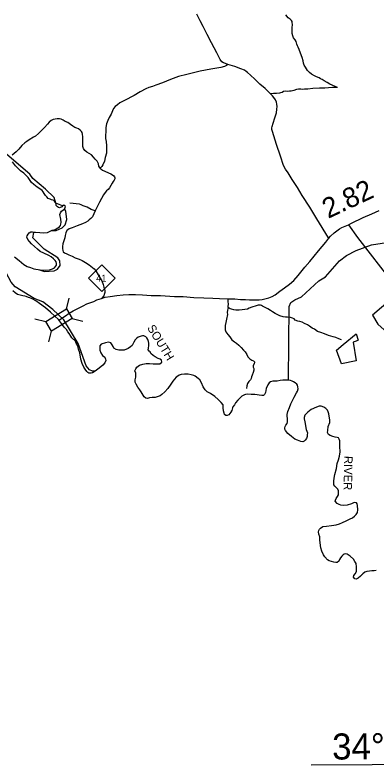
# Model space of a CAD drawing. Extents: x 2093524 to 2270757, y 289120 to 570408.
# Drawn here: x 2188536 to 2197553, y 334062 to 352773 of the extents above; entities that cross this region are included whole.
import ezdxf

# ---------------------------------------------------------------- set-up
doc = ezdxf.new("R2010")
doc.units = 0
for name, color, linetype in [('Exist Boundary Political CountyLine', 7, 'Continuous'), ('Exist Hydrographic Creek Single Shore', 7, 'Continuous'), ('Exist Hydrographic Lagoon', 7, 'Continuous'), ('Exist Hydrographic Misc Water Feature', 7, 'Continuous'), ('Exist Hydrographic River Shore Label', 7, 'Continuous'), ('Exist Road Non-System Type 51', 7, 'Continuous'), ('Exist Road Primary NC Attributed', 7, 'Continuous'), ('Exist Road Primary NC Service Mileage Hundredths English Label', 7, 'Continuous'), ('Exist Road Primary NC Shield CELL', 7, 'Continuous'), ('Exist Road Primary NC Shield Number Label', 7, 'Continuous'), ('Exist Road Primary NC Structure Standard Bridge CELL', 7, 'Continuous'), ('Map Preparation Longitude Latitude Label', 7, 'Continuous'), ('Map Preparation Longitude Latitude Lines', 7, 'Continuous')]:
    doc.layers.add(name, color=color, linetype=linetype)

msp = doc.modelspace()

# ---------------------------------------------------------------- linework, layer by layer
at = {"layer": 'Exist Boundary Political CountyLine'}
for points in [[(2189050, 347357), (2189159, 347345), (2189256, 347337), (2189346, 347350), (2189465, 347403), (2189536, 347422), (2189606, 347459), (2189645, 347490), (2189672, 347520), (2189681, 347554), (2189686, 347605), (2189681, 347680), (2189657, 347799), (2189669, 347838), (2189696, 347879), (2189758, 347922), (2189784, 347949), (2189797, 347997), (2189758, 348031), (2189734, 348017), (2189702, 347988), (2189651, 347958), (2189619, 347968), (2189598, 347988), (2189568, 348019), (2189561, 348068), (2189537, 348104), (2189512, 348145), (2189481, 348153), (2189449, 348158), (2189413, 348175), (2189362, 348194), (2189328, 348233), (2189296, 348267), (2189264, 348318), (2189240, 348357), (2189211, 348396), (2189160, 348437), (2189094, 348474), (2189007, 348542), (2188951, 348598), (2188915, 348646), (2188868, 348717), (2188818, 348770), (2188759, 348824), (2188672, 348887), (2188616, 348943), (2188552, 349006), (2188470, 349108)], [(2188527, 346739), (2188639, 346647), (2188753, 346550), (2188840, 346496), (2188921, 346470), (2189008, 346436), (2189161, 346416), (2189300, 346404), (2189394, 346414), (2189472, 346436), (2189521, 346467), (2189552, 346501), (2189572, 346535), (2189574, 346572), (2189565, 346611), (2189538, 346650), (2189502, 346686), (2189441, 346739), (2189378, 346776), (2189256, 346832), (2189166, 346871), (2189100, 346931), (2189025, 347000), (2188950, 347063), (2188899, 347121), (2188860, 347172), (2188836, 347230), (2188843, 347264), (2188862, 347303), (2188887, 347335), (2188935, 347364), (2188972, 347364), (2189050, 347357)], [(2190798, 344186), (2190803, 344150), (2190776, 344094), (2190734, 344040), (2190640, 343965), (2190538, 343885), (2190470, 343846), (2190436, 343836), (2190406, 343836), (2190380, 343841), (2190353, 343856), (2190329, 343882), (2190292, 343933), (2190258, 343989), (2190212, 344079), (2190178, 344186), (2190152, 344342), (2190125, 344439), (2190103, 344517), (2190064, 344587), (2190035, 344650), (2190001, 344677), (2189957, 344721), (2189935, 344762), (2189889, 344825), (2189860, 344872), (2189821, 344928), (2189763, 344981), (2189719, 345044), (2189622, 345173), (2189534, 345260), (2189427, 345358), (2189294, 345470), (2189150, 345572), (2189053, 345640), (2188978, 345683), (2188907, 345713), (2188874, 345728), (2188819, 345750), (2188780, 345762), (2188734, 345770), (2188666, 345782), (2188600, 345801), (2188544, 345838), (2188481, 345894)], [(2193833, 342781), (2193801, 342781), (2193772, 342806), (2193757, 342842), (2193745, 342901), (2193738, 342971), (2193732, 343050), (2193683, 343108), (2193608, 343184), (2193530, 343257), (2193423, 343332), (2193338, 343373), (2193290, 343424), (2193238, 343495), (2193197, 343592), (2193156, 343667), (2193111, 343700), (2193040, 343761), (2193002, 343780), (2192936, 343797), (2192858, 343810), (2192766, 343812), (2192686, 343800), (2192637, 343790), (2192601, 343766), (2192564, 343737), (2192518, 343686), (2192477, 343635), (2192431, 343562), (2192350, 343455), (2192278, 343372), (2192207, 343309), (2192158, 343272), (2192112, 343255), (2192040, 343234), (2191964, 343226), (2191898, 343219), (2191848, 343209), (2191804, 343214), (2191760, 343248), (2191736, 343287), (2191687, 343370), (2191658, 343421), (2191607, 343491), (2191566, 343562), (2191541, 343610), (2191541, 343669), (2191551, 343734), (2191556, 343778), (2191554, 343839), (2191532, 343895), (2191551, 343943), (2191578, 343987), (2191646, 344040), (2191728, 344065), (2191811, 344077), (2191898, 344079), (2191988, 344072), (2192151, 344074), (2192200, 344108), (2192195, 344160), (2192161, 344184), (2192110, 344203), (2192040, 344245), (2191988, 344279), (2191932, 344327), (2191911, 344369), (2191884, 344390), (2191862, 344422), (2191867, 344463), (2191882, 344526), (2191879, 344585), (2191867, 344629), (2191852, 344675), (2191830, 344716), (2191806, 344745), (2191750, 344770), (2191719, 344767), (2191687, 344762), (2191614, 344738), (2191578, 344709), (2191541, 344672), (2191507, 344607), (2191461, 344531), (2191422, 344490), (2191359, 344454), (2191262, 344412), (2191204, 344407), (2191133, 344415), (2191063, 344429), (2191004, 344461), (2190987, 344502), (2190966, 344548), (2190929, 344590), (2190871, 344614), (2190793, 344597), (2190688, 344563), (2190659, 344517), (2190652, 344468), (2190652, 344415)], [(2190652, 344415), (2190679, 344342), (2190720, 344279), (2190776, 344237), (2190798, 344186)], [(2196634, 342193), (2196617, 342220), (2196581, 342235), (2196537, 342244), (2196476, 342261), (2196404, 342278), (2196367, 342310), (2196343, 342356), (2196348, 342407), (2196357, 342507), (2196396, 342604), (2196396, 342672), (2196386, 342764), (2196374, 342825), (2196360, 342869), (2196338, 342913), (2196299, 342959), (2196246, 342990), (2196185, 343012), (2196131, 343010), (2196068, 342988), (2195937, 342927), (2195852, 342866), (2195806, 342825), (2195776, 342786), (2195760, 342735), (2195762, 342699), (2195776, 342623), (2195810, 342431), (2195840, 342351), (2195837, 342300), (2195835, 342254), (2195813, 342210), (2195784, 342164), (2195760, 342137), (2195728, 342123), (2195674, 342135), (2195592, 342162), (2195524, 342193), (2195444, 342254), (2195349, 342334), (2195296, 342407), (2195278, 342444), (2195276, 342470), (2195283, 342504), (2195300, 342538), (2195330, 342580), (2195342, 342623), (2195344, 342667), (2195342, 342716), (2195332, 342760), (2195334, 342808), (2195351, 342879), (2195389, 342977), (2195427, 343076), (2195512, 343241), (2195568, 343345), (2195590, 343384), (2195606, 343445), (2195604, 343498), (2195594, 343537), (2195572, 343564), (2195536, 343596), (2195492, 343620), (2195456, 343637), (2195419, 343654), (2195378, 343659), (2195308, 343664), (2195225, 343664), (2195162, 343652), (2195082, 343637), (2195016, 343635), (2194977, 343635), (2194919, 343618), (2194887, 343598), (2194851, 343545), (2194810, 343455), (2194797, 343355), (2194766, 343309), (2194742, 343282), (2194700, 343277), (2194634, 343289), (2194586, 343294), (2194528, 343302), (2194435, 343306), (2194355, 343314), (2194294, 343306), (2194265, 343294), (2194202, 343260), (2194105, 343165), (2194042, 343100), (2194022, 343051), (2193981, 343000), (2193969, 342971), (2193964, 342939), (2193956, 342905), (2193925, 342866), (2193906, 342828), (2193881, 342801), (2193833, 342781)], [(2197561, 338913), (2197503, 338908), (2197447, 338904), (2197394, 338896), (2197327, 338885), (2197273, 338871), (2197222, 338834), (2197164, 338771), (2197110, 338725), (2197057, 338698), (2197028, 338706), (2196994, 338749), (2197001, 338791), (2197035, 338834), (2197064, 338893), (2197069, 338944), (2197067, 339004), (2197055, 339085), (2197023, 339136), (2196989, 339194), (2196909, 339269), (2196829, 339318), (2196795, 339328), (2196756, 339318), (2196729, 339303), (2196700, 339272), (2196668, 339233), (2196637, 339189), (2196624, 339145), (2196586, 339111), (2196547, 339111), (2196498, 339121), (2196438, 339136), (2196384, 339158), (2196345, 339182), (2196275, 339255), (2196243, 339308), (2196199, 339393), (2196178, 339476), (2196148, 339668), (2196146, 339753), (2196126, 339819), (2196117, 339875), (2196124, 339913), (2196141, 339948), (2196165, 339972), (2196226, 340008), (2196316, 340020), (2196440, 340035), (2196554, 340057), (2196644, 340079), (2196717, 340110), (2196804, 340152), (2196911, 340200), (2196962, 340232), (2197018, 340271), (2197055, 340312), (2197089, 340363), (2197098, 340424), (2197094, 340536), (2197084, 340579), (2197064, 340601), (2197004, 340611), (2196943, 340579), (2196836, 340548), (2196736, 340536), (2196676, 340541), (2196630, 340558), (2196586, 340582), (2196535, 340640), (2196540, 340669), (2196559, 340708), (2196593, 340759), (2196620, 340805), (2196620, 340861), (2196620, 340905), (2196603, 340944), (2196556, 340983), (2196522, 341017), (2196501, 341053), (2196498, 341146), (2196508, 341221), (2196525, 341309), (2196566, 341459), (2196583, 341586), (2196612, 341678), (2196637, 341768), (2196654, 341875), (2196651, 342011), (2196646, 342147), (2196634, 342193)]]:
    msp.add_lwpolyline(points, dxfattribs=at)
at = {"layer": 'Exist Hydrographic Creek Single Shore'}
msp.add_lwpolyline([(2195369, 343671), (2195382, 345498), (2195423, 345599), (2195522, 345665), (2195696, 345741), (2196127, 346142), (2196293, 346244), (2196640, 346637), (2196814, 346772), (2197055, 346898), (2197437, 347035), (2198029, 347131), (2198111, 347199), (2198201, 347384), (2198268, 347392)], dxfattribs=at)
at = {"layer": 'Exist Hydrographic Lagoon'}
msp.add_lwpolyline([(2196729, 344551), (2197061, 344817), (2197104, 344658), (2197061, 344638), (2196983, 344609), (2197055, 344144), (2196688, 344066), (2196567, 344412)], close=True, dxfattribs=at)
at = {"layer": 'Exist Hydrographic Misc Water Feature'}
msp.add_line((2197185, 338803), (2197198, 338809), dxfattribs=at)
for points in [[(2189726, 348010), (2189553, 348082), (2189515, 348222), (2189297, 348429), (2188979, 348695), (2188903, 348801), (2188275, 349345), (2187908, 349553)], [(2189447, 347395), (2189563, 347397), (2189712, 347467), (2189786, 347541), (2189827, 347674), (2189809, 347875), (2189773, 347937)], [(2189270, 346370), (2189511, 346388), (2189594, 346432), (2189668, 346523), (2189659, 346641), (2189609, 346714), (2189266, 346931), (2188981, 347212), (2189005, 347343), (2189039, 347358)], [(2189016, 345696), (2188539, 345991), (2188438, 346108), (2188194, 346572), (2188160, 346681), (2188175, 346805), (2188233, 346873), (2188295, 346877)], [(2189149, 346417), (2189270, 346370)], [(2190470, 343889), (2190394, 343920), (2190310, 344020), (2190115, 344579), (2189753, 345166), (2189484, 345424), (2189233, 345613), (2189016, 345696)], [(2190544, 343890), (2190470, 343889)], [(2195369, 343671), (2195343, 343661)], [(2193939, 342884), (2193925, 342879)], [(2196627, 339153), (2196617, 339149)]]:
    msp.add_lwpolyline(points, dxfattribs=at)
at = {"layer": 'Exist Road Non-System Type 51'}
for points in [[(2193850, 351534), (2193797, 351559), (2193741, 351581), (2193703, 351604), (2193663, 351660), (2193576, 351832), (2193448, 352079), (2193337, 352286), (2193235, 352483), (2193160, 352630), (2193079, 352790)], [(2196588, 350961), (2196402, 351047), (2196334, 351087), (2196258, 351130), (2196205, 351164), (2196167, 351184), (2196135, 351203), (2196065, 351227), (2196013, 351253), (2195938, 351300), (2195894, 351340), (2195842, 351389), (2195789, 351471), (2195757, 351525), (2195741, 351571), (2195730, 351633), (2195708, 351714), (2195669, 351820), (2195630, 351916), (2195608, 351968), (2195590, 352005), (2195576, 352041), (2195571, 352075), (2195561, 352109), (2195537, 352157), (2195496, 352205), (2195472, 352251), (2195460, 352312), (2195457, 352386), (2195463, 352464), (2195468, 352530), (2195462, 352592), (2195455, 352614), (2195445, 352634), (2195429, 352650), (2195411, 352668), (2195385, 352682), (2195357, 352702), (2195301, 352775)], [(2193850, 351534), (2193820, 351517), (2193770, 351485), (2193680, 351466), (2193431, 351423), (2193161, 351375), (2192830, 351291), (2192624, 351237), (2192554, 351215), (2192419, 351166), (2192221, 351082), (2192054, 351019), (2191972, 350993), (2191878, 350960), (2191805, 350932), (2191661, 350855), (2191512, 350766), (2191273, 350636), (2191151, 350579), (2191096, 350535), (2191034, 350490), (2190996, 350436), (2190975, 350384), (2190935, 350302), (2190890, 350216), (2190854, 350139), (2190825, 350057), (2190804, 349965), (2190802, 349867), (2190795, 349767), (2190800, 349691), (2190814, 349613), (2190821, 349507), (2190824, 349407), (2190818, 349325), (2190785, 349219), (2190769, 349129), (2190728, 349037), (2190704, 348995), (2190667, 348955)], [(2194920, 350803), (2194781, 350936), (2194651, 351049), (2194524, 351170), (2194415, 351270), (2194345, 351335), (2194309, 351367), (2194266, 351399), (2194178, 351428), (2194024, 351491), (2193850, 351534)], [(2196588, 350961), (2196537, 350960), (2196465, 350960), (2196369, 350957), (2196271, 350948), (2196143, 350946), (2195973, 350935), (2195851, 350922), (2195763, 350921), (2195719, 350917), (2195679, 350922), (2195653, 350922), (2195621, 350924), (2195567, 350912), (2195499, 350889), (2195430, 350871), (2195390, 350870), (2195338, 350868), (2195284, 350870), (2195244, 350863), (2195208, 350839), (2195168, 350827), (2195142, 350821), (2195066, 350812), (2194996, 350812), (2194920, 350803)], [(2196382, 347187), (2196324, 347284), (2196209, 347473), (2196077, 347684), (2195897, 347977), (2195711, 348266), (2195596, 348469), (2195463, 348670), (2195358, 348835), (2195291, 348930), (2195242, 349022), (2195167, 349251), (2195071, 349539), (2195001, 349762), (2194965, 349868), (2194954, 349914), (2194952, 349956), (2194962, 349992), (2194985, 350078), (2195030, 350210), (2195065, 350332), (2195079, 350422), (2195086, 350489), (2195078, 350546), (2195069, 350598), (2195043, 350654), (2195003, 350714), (2194969, 350754), (2194920, 350803)], [(2190667, 348955), (2190630, 349000), (2190622, 349062), (2190588, 349126), (2190539, 349179), (2190495, 349225), (2190447, 349281), (2190388, 349314), (2190334, 349348), (2190282, 349394), (2190249, 349439), (2190233, 349491), (2190229, 349581), (2190232, 349659), (2190227, 349737), (2190225, 349799), (2190215, 349841), (2190197, 349867), (2190160, 349897), (2190120, 349932), (2190078, 349952), (2190034, 349964), (2189978, 350003), (2189924, 350045), (2189855, 350088), (2189791, 350112), (2189737, 350150), (2189689, 350171), (2189649, 350179), (2189591, 350183), (2189541, 350178), (2189489, 350164), (2189443, 350140), (2189393, 350099), (2189346, 350053), (2189272, 349967), (2189193, 349882), (2189127, 349813), (2189046, 349753), (2188998, 349729), (2188893, 349660), (2188829, 349618), (2188779, 349581), (2188706, 349513), (2188632, 349428), (2188565, 349358), (2188465, 349273)], [(2190667, 348955), (2190679, 348933), (2190721, 348899), (2190781, 348877), (2190875, 348838), (2190927, 348810), (2190968, 348783), (2191004, 348757), (2191022, 348739), (2191026, 348713), (2191026, 348687), (2191017, 348655), (2190985, 348617), (2190961, 348577), (2190926, 348522), (2190894, 348462), (2190860, 348418), (2190823, 348382), (2190785, 348346), (2190745, 348287), (2190696, 348191), (2190651, 348105), (2190609, 348019), (2190538, 347890)], [(2190538, 347890), (2190440, 347923), (2190342, 347979), (2190243, 348010), (2190187, 348037), (2190147, 348057), (2189907, 348078)], [(2190538, 347890), (2190509, 347810), (2190469, 347740), (2190432, 347695), (2190392, 347659), (2190354, 347629), (2190294, 347598), (2190226, 347566), (2190089, 347511), (2189967, 347464), (2189886, 347436), (2189858, 347414), (2189834, 347393), (2189810, 347341), (2189793, 347269), (2189781, 347215), (2189752, 347135), (2189734, 347061), (2189720, 346997), (2189721, 346945), (2189727, 346899), (2189743, 346867), (2189770, 346837), (2189828, 346811), (2189880, 346792), (2189960, 346754), (2190040, 346715), (2190138, 346680), (2190215, 346644), (2190297, 346601), (2190391, 346538), (2190468, 346476), (2190516, 346438), (2190556, 346389), (2190615, 346293), (2190666, 346210), (2190704, 346142), (2190741, 346052), (2190759, 345986), (2190771, 345938), (2190782, 345890), (2190782, 345849), (2190774, 345824), (2190753, 345770), (2190695, 345702)], [(2196862, 347541), (2197090, 347223), (2197980, 346076), (2198104, 345920), (2198118, 345886), (2198107, 345845), (2198081, 345805), (2197468, 345285), (2197601, 345057), (2198303, 344427), (2198384, 344337), (2198673, 343904), (2198763, 343817), (2199026, 343531), (2199317, 343266), (2199852, 342904), (2200250, 342607), (2200363, 342477), (2200432, 342338), (2200571, 341590)], [(2193861, 345474), (2193863, 345496), (2193871, 345566), (2193864, 345618), (2193864, 345692)], [(2193861, 345474), (2193840, 345406), (2193836, 345348), (2193840, 345298), (2193821, 345186), (2193804, 345103), (2193784, 345023), (2193783, 344962), (2193787, 344917), (2193804, 344870), (2193848, 344804), (2193898, 344744), (2193951, 344671), (2194017, 344619), (2194065, 344586), (2194130, 344538), (2194188, 344474), (2194246, 344411), (2194283, 344373), (2194323, 344301), (2194352, 344244), (2194398, 344198), (2194452, 344160), (2194490, 344143), (2194510, 344131), (2194514, 344117), (2194519, 344099), (2194513, 344079), (2194487, 344021), (2194487, 343985), (2194500, 343955), (2194502, 343913), (2194488, 343857), (2194459, 343785), (2194447, 343746), (2194439, 343706), (2194418, 343670), (2194380, 343630), (2194346, 343578), (2194329, 343520), (2194321, 343454)], [(2196690, 344671), (2196626, 344691), (2196547, 344723), (2196479, 344742), (2196367, 344775), (2196263, 344817), (2196173, 344850), (2196095, 344877), (2196014, 344931), (2195958, 344963), (2195890, 345008), (2195839, 345046), (2195767, 345079), (2195707, 345109), (2195653, 345122), (2195599, 345134), (2195533, 345163), (2195507, 345191), (2195469, 345211), (2195418, 345227), (2195342, 345232), (2195296, 345232), (2195236, 345241), (2195150, 345271), (2195038, 345328), (2194970, 345367), (2194915, 345403), (2194851, 345445), (2194783, 345478), (2194717, 345512), (2194689, 345524), (2194665, 345531), (2194639, 345531), (2194609, 345531), (2194559, 345513), (2194449, 345486), (2194389, 345459), (2194343, 345433), (2194278, 345427), (2194214, 345416), (2194138, 345408), (2194050, 345407), (2194006, 345419), (2193944, 345436), (2193910, 345444), (2193861, 345474)]]:
    msp.add_lwpolyline(points, dxfattribs=at)
at = {"layer": 'Exist Road Primary NC Attributed'}
msp.add_lwpolyline([(2189631, 345160), (2189796, 345268), (2189886, 345330), (2189992, 345389), (2190119, 345462), (2190235, 345521), (2190332, 345563), (2190502, 345629), (2190577, 345665), (2190695, 345702), (2190787, 345730), (2190917, 345747), (2191078, 345774), (2191240, 345790), (2191382, 345799), (2191548, 345798), (2191722, 345791), (2191940, 345778), (2192174, 345772), (2192522, 345753), (2192738, 345746), (2193002, 345726), (2193256, 345720), (2193474, 345711), (2193644, 345700), (2193864, 345692), (2194024, 345689), (2194168, 345678), (2194294, 345673), (2194390, 345667), (2194512, 345664), (2194632, 345663), (2194708, 345674), (2194777, 345692), (2194879, 345715), (2194961, 345751), (2195031, 345792), (2195150, 345879), (2195267, 345965), (2195391, 346058), (2195504, 346153), (2195607, 346270), (2195773, 346479), (2195897, 346624), (2196114, 346890), (2196299, 347109), (2196373, 347201), (2196419, 347254), (2196509, 347342), (2196645, 347440), (2196699, 347469), (2196862, 347541), (2196938, 347580), (2197231, 347718), (2197447, 347816), (2197631, 347895)], dxfattribs=at)
at = {"layer": 'Exist Road Primary NC Shield CELL'}
msp.add_lwpolyline([(2190374, 346208), (2190707, 346541), (2191040, 346208), (2190707, 345875)], close=True, dxfattribs=at)
at = {"layer": 'Exist Road Primary NC Structure Standard Bridge CELL'}
for p, q in [((2189821, 345437), (2189887, 345705)), ((2189035, 345191), (2189303, 345125)), ((2189964, 345201), (2190232, 345135)), ((2189384, 344616), (2189449, 344884))]:
    msp.add_line(p, q, dxfattribs=at)
msp.add_lwpolyline([(2189303, 345125), (2189820, 345438), (2189967, 345197), (2189449, 344884)], close=True, dxfattribs=at)
at = {"layer": 'Map Preparation Longitude Latitude Lines'}
msp.add_lwpolyline([(2195934, 334062), (2200496, 334090), (2204485, 334119)], dxfattribs=at)

# ---------------------------------------------------------------- texts
at = {"layer": 'Exist Hydrographic River Shore Label'}
for s, rotation, p in [('SOUTH', 301.6365, (2191830, 344966)), ('RIVER', 268.8327, (2196760, 341775))]:
    msp.add_text(s, height=210, rotation=rotation, dxfattribs=at).set_placement(p)
at = {"layer": 'Exist Road Primary NC Service Mileage Hundredths English Label'}
msp.add_text('2.82', height=500, rotation=25.0854, dxfattribs=at).set_placement((2196357, 347685))
at = {"layer": 'Exist Road Primary NC Shield Number Label'}
msp.add_text('41', height=175, dxfattribs=at).set_placement((2190561, 346118))
at = {"layer": 'Map Preparation Longitude Latitude Label'}
msp.add_text("34° 40'", height=650, rotation=0.3607, dxfattribs=at).set_placement((2196459, 334197))

doc.saveas('drawing.dxf')
